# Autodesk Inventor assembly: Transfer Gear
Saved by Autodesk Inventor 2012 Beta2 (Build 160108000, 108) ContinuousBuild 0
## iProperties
Created: 2011-01
Part Number: Transfer Gear
Document SubType Name: Assembly
Designer: Beta-8540w
Categories: <?xml version="1.0" encoding="UTF-16"?> <MemberInstance><Categories><FamilyTemplate/><ParamToTemplateMap><ParamToTemplate><ParamToTemplate CategoryParameter="//
ClientObjectVersion: 1
Author: Beta-8540w
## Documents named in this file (1)
- C:\Inventor 2012 Essentials\Assemblies\Chapter 8\Design Accelerators\Gear c8-01.iam
